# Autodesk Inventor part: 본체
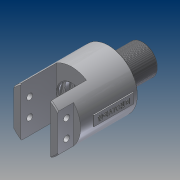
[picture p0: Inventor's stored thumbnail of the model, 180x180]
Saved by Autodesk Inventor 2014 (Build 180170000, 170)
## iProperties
Created: 2019-02
Part Number: 본체
Material: 알루미늄 6061
Document SubType Name: Modeling
Designer: 603-18
Density: 2.71 g/cm^3
Appearance: 알루미늄 - 평지
Mass: 344.106 g
Surface Area: 281.944 cm^2
Volume: 126.976 cm^3
Author: 603-18
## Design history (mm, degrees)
sketch "스케치1"
  geometry: L1 (-37, 0)-(37, 0); L2 (-37, 0)-(-37, 22); L3 (-1, 29)-(37, 29); L4 (37, 29)-(37, 0); L5 (26, 0)-(26, 16); L6 (19, 16)-(19, 14); L7 (19, 14)-(15.35, 14); L8 (15.35, 14)-(15.35, 16.2); L9 (14.55, 17)-(11.45, 17); L10 (10.65, 16.2)-(10.65, 14); L11 (10.65, 14)-(6.35, 14); L12 (5.55, 17)-(2.45, 17); L13 (1.65, 16.2)-(1.65, 14); L14 (1.65, 14)-(-1, 14); L15 (-1, 14)-(-1, 0); L16 (6.35, 14)-(6.35, 16.2); L17 (-1, 29)-(-37, 29); L18 (-37, 29)-(-37, 22); L19 (19, 16)-(26, 16); A1 r 0.8 centre (2.45, 16.2) between (2.45, 17) and (1.65, 16.2); A2 r 0.8 centre (5.55, 16.2) between (6.35, 16.2) and (5.55, 17); A3 r 0.8 centre (11.45, 16.2) between (11.45, 17) and (10.65, 16.2); A4 r 0.8 centre (14.55, 16.2) between (15.35, 16.2) and (14.55, 17); 5 further points
  constraints: 38 end point, 9 parallel, 8 point on circle, 8 tangent, 5 perpendicular, 4 centre point, 4 horizontal alignment, 3 equal radius, 3 midpoint, 2 horizontal, 2 point on line, 1 coincident, 1 collinear
  dimensions: "d0" = 74 distance of L1.start L1.end; "d1" = 20 distance between parallel lines of L15 L6; "d2" = 27 distance between parallel lines of L15 L5; "d3" = 28 diameter of L14 L1; "d5" = 58 diameter of L3 L1; "d6" = 4.7 distance between parallel lines of L16 L13; "d7" = 4.7 distance between parallel lines of L8 L10; "d11" = 5 distance from line of L15 point (4, 17); "d12" = 9 distance of point (13, 17) point (4, 17); "d13" = 0.8 radius of A1; "d42" = 36 distance between parallel lines of L2 L15; "d81" = 34 diameter of point (4, 17) L1; "d82" = 32 diameter of L19 L1; "d83" = 7 distance between parallel lines of L5 L6 (derived); "d84" = 0.8 radius of A4 (derived)
revolve "회전1" stored, may be unused: angle "d15" = 90 deg
sketch "스케치4"
  geometry: C1 r 29 at (0, 0) reference; C2 r 14 at (0, 0)
  constraints: 1 centre point, 1 coincident
  dimensions: "d22" = 28 diameter of C2
extrude "돌출2" join sketch "스케치4" distance "d23" = 5; taper "d24" = 0 deg
sketch "스케치5"
  geometry: C1 r 14 at (0, 0) reference; C2 r 15 at (0, 0)
  constraints: 1 centre point, 1 coincident
  dimensions: "d25" = 30 diameter of C2
extrude "돌출3" join sketch "스케치5" distance "d26" = 29; taper "d27" = 0 deg
feature "스레드1" dims "d28" = 10, "d29" = 0
sketch "스케치6"
  geometry: C1 r 15 at (0, 0) reference
hole "구멍1" diameter "d32" = 12.376; stored, may be unused: countersink angle "d36" = 90 deg, drill point angle "d38" = 118 deg; dims "d30" = 10, "d31" = 10, "d33" = 18, "d34" = 4, "d35" = 2, "d37" = 22
sketch "스케치7"
  geometry: C1 r 16 at (0, 0) reference; C2 r 4 at (0, 0)
  constraints: 1 centre point, 1 coincident
  dimensions: "d39" = 8 diameter of C2
extrude "돌출4" cut sketch "스케치7" stored distance "d40" = 22; taper "d41" = 0 deg
sketch "스케치8"
  geometry: C1 r 29 at (0, 0) reference; C2 r 15 at (0, 0)
  constraints: 1 centre point, 1 coincident
  dimensions: "d43" = 30 diameter of C2
extrude "돌출5" cut sketch "스케치8" distance "d44" = 36; taper "d45" = 0 deg
sketch "스케치9"
  geometry: L1 (-22, 18.894)-(-22, -18.894); L2 (22, 18.894)-(22, -18.894); L3 (-15, 24.819)-(-15, -24.819); L4 (15, 24.819)-(15, -24.819); C1 r 15 at (0, 0) reference; A1 r 29 centre (0, 0) between (22, 18.894) and (-22, 18.894); A2 r 29 centre (0, 0) between (-22, -18.894) and (22, -18.894); A3 r 29 centre (0, 0) between (-22, 18.894) and (-22, -18.894); A4 r 29 centre (0, 0) between (22, -18.894) and (22, 18.894); 1 further point
  constraints: 12 point on circle, 8 end point, 4 centre point, 4 concentric, 3 vertical, 1 parallel, 10 other
  dimensions: "d46" = 22 distance from line of L2 C1.centre; "d47" = 22 distance from line of L1 C1.centre; "d48" = 15 distance from line of L4 C1.centre; "d49" = 15 distance from line of L3 C1.centre
extrude "돌출6" cut sketch "스케치9" distance "d50" = 36; taper "d51" = 0 deg
extrude "돌출7" cut sketch "스케치9" distance "d52" = 16; taper "d53" = 0 deg
sketch "스케치10"
  geometry: L1 (0, 0)-(0, 37.789) reference; L2 (0, 37.789)-(16, 37.789) reference; L3 (0, 18.894)-(73.46, 18.894); C1 r 3 at (9, 27.894); C2 r 3 at (9, 9.894); 1 further point
  constraints: 2 centre point, 2 end point, 1 midpoint, 1 parallel, 1 vertical alignment
  dimensions: "d54" = 6 diameter of C1; "d55" = 6 diameter of C2; "d56" = 9 distance from line of L1 C1.centre; "d57" = 18 distance of C2.centre C1.centre; "d59" = 9 distance from line of L3 C1.centre
extrude "돌출8" cut sketch "스케치10" distance "d60" = 16; taper "d61" = 0 deg
chamfer "모따기2" distance "d62" = 1; stored, may be unused: second distance "d63" = 2, angle "d64" = 45 deg
chamfer "모따기3" distance "d65" = 1; stored, may be unused: second distance "d66" = 2, angle "d67" = 45 deg
node "작업 평면1"
sketch "스케치11"
  geometry: L1 (-8, 5)-(32, 5); L2 (32, 5)-(32, -5); L3 (32, -5)-(-8, -5); L4 (-8, -5)-(-8, 5); L5 (37, 28)-(37, -28) reference; 2 further points
  constraints: 8 end point, 2 parallel, 1 horizontal, 1 horizontal alignment, 1 midpoint, 1 perpendicular
  dimensions: "d69" = 40 distance between parallel lines of L2 L4; "d70" = 5 distance between parallel lines of L5 L2; "d71" = 10 distance between parallel lines of L3 L1
extrude "돌출9" join sketch "스케치11" stored distance "d72" = 16; taper "d73" = 0 deg
sketch "스케치12"
  geometry: L1 (-8, -5)-(-8, 5) reference; L2 (32, -5)-(-8, -5) reference; 2 further points
  constraints: 1 other
  dimensions: "d74" = 20 distance from line of L1 point (12, 0); "d75" = 5 distance from line of L2 point (12, 0)
feature "엠보싱1" sketch "스케치12" dims "d76" = 0.5, "d77" = 0
chamfer "모따기4" distance "d78" = 1; stored, may be unused: second distance "d79" = 2, angle "d80" = 45 deg
node "솔리드1"
mirror "대칭1"
mirror "대칭2"
other parameters: "d68" = 29.5
